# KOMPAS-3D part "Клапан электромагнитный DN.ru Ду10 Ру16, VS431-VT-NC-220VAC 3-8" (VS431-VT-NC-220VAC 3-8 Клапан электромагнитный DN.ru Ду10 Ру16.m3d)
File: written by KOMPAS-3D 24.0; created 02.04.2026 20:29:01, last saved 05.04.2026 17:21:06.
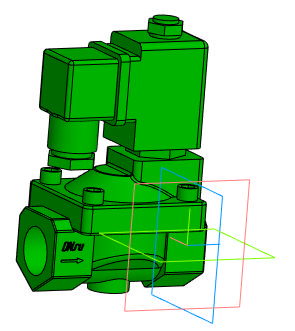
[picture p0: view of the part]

Document properties: Автор: artio; Полное имя файла: C:\Users\artio\OneDrive\Рабочий стол\Клапан электромагнитный DN.ru\VS431\VS431-VT-NC\VS431-VT-NC-220VAC\Ду10\VS431-VT-NC-220VAC 3-8 Клапан электромагнитный DN.ru Ду10 Ру16.m3d

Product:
- Body: Тело 1  | qty 1
    Масса: 1.030062
- Part/product: Клапан электромагнитный DN.ru Ду10 Ру16  | designation VS431-VT-NC-220VAC 3-8
    Масса: 0.62
    Раздел спецификации: Прочие изделия
    Примечание: D130-04711
    additional columns: ef56311e-7521-43dc-8291-0e6108b3d81d; VS400-ET-NC-220VAC 3-8; artio; c; Шероховатость не задана; Да

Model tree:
1. Операция без истории:1

Expressions: VS431-VT-NC-220VAC 3-8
